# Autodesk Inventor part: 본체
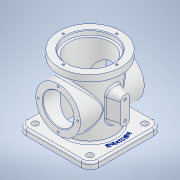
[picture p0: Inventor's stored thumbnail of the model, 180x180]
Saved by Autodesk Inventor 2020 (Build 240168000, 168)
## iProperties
Created: 2021-03
Part Number: 본체
Material: 알루미늄 6061
Document SubType Name: Modeling
Designer: USER
Density: 2.7 g/cm^3
Appearance: 알루미늄 - 평지
Mass: 830.909 g
Surface Area: 863.889 cm^2
Volume: 307.744 cm^3
Author: USER
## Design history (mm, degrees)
sketch "스케치1"
  geometry: L1 (57, -57)-(-57, -57); L2 (-57, -57)-(-57, 57); L3 (-57, 57)-(57, 57); L4 (57, 57)-(57, -57); L5 (57, -57)-(-57, 57); L6 (-57, -57)-(57, 57); 1 further point
  constraints: 12 end point, 2 midpoint, 2 parallel, 1 horizontal, 1 perpendicular
  dimensions: "d0" = 114 distance of L1.start L1.end; "d1" = 114 distance of L1.end L2.end
extrude "돌출1" new body sketch "스케치1" distance "d2" = 10; taper "d3" = 0 deg
sketch "스케치2"
  geometry: C1 r 38 at (0, 0); 1 further point
  constraints: 1 centre point, 1 coincident
  dimensions: "d4" = 76 diameter of C1
extrude "돌출2" join sketch "스케치2" distance "d5" = 101; taper "d6" = 0 deg
sketch "스케치3"
  geometry: C1 r 49 at (0, 0); 1 further point
  constraints: 1 centre point, 1 coincident
  dimensions: "d7" = 98 diameter of C1
extrude "돌출3" join sketch "스케치3" distance "d8" = 13; taper "d9" = 0 deg
sketch "스케치4"
  geometry: L1 (57, 0)-(-57, 0) reference; C1 r 35 at (0, 54); 2 further points
  constraints: 1 centre point, 1 midpoint, 1 vertical alignment
  dimensions: "d10" = 54 distance from line of C1.centre L1; "d11" = 70 diameter of C1
extrude "돌출4" join sketch "스케치4" stored distance "d12" = 100; taper "d13" = 0 deg
sketch "스케치5"
  geometry: C1 r 38 at (0, 0) reference; 2 further points
  constraints: 1 coincident
hole "구멍1" sketch "스케치5" at (0, 0) diameter "d14" = 66; stored, may be unused: countersink angle "d18" = 90 deg, drill point angle "d20" = 118 deg; dims "d15" = 6, "d16" = 74, "d17" = 7, "d19" = 8
sketch "스케치6"
  geometry: C1 r 35 at (0, 0) reference; 2 further points
  constraints: 1 coincident
hole "구멍2" sketch "스케치6" at (0, 0) diameter "d21" = 48; stored, may be unused: countersink angle "d25" = 90 deg, drill point angle "d27" = 118 deg; dims "d22" = 6, "d23" = 74, "d24" = 7, "d26" = 8
sketch "스케치7" dims "d28" = 62
  geometry: C1 r 35 at (0, 0) reference; 3 further points
  constraints: 2 vertical alignment, 1 coincident, 2 other
hole "구멍3" sketch "스케치7" at (0, 31) diameter "d29" = 3.242; stored, may be unused: countersink angle "d33" = 90 deg, drill point angle "d35" = 118 deg; dims "d30" = 6, "d31" = 74, "d32" = 7, "d34" = 8
sketch "스케치8" dims "d39" = 84
  geometry: C1 r 49 at (0, 0) reference; 3 further points
  constraints: 2 horizontal alignment, 1 coincident, 2 other
hole "구멍4" sketch "스케치8" at (-42, 0) diameter "d40" = 3.242; stored, may be unused: countersink angle "d44" = 90 deg, drill point angle "d46" = 118 deg; dims "d41" = 6, "d42" = 74, "d43" = 7, "d45" = 8
fillet "모깎기1" dims "d50" = 14
sketch "스케치9"
  geometry: A1 r 14 centre (-43, -43) between (-57, -43) and (-43, -57) reference; A2 r 14 centre (-43, 43) between (-43, 57) and (-57, 43) reference; A3 r 14 centre (43, 43) between (57, 43) and (43, 57) reference; A4 r 14 centre (43, -43) between (43, -57) and (57, -43) reference; 5 further points
  constraints: 4 coincident
hole "구멍5" sketch "스케치9" at (-43, -43), (-43, 43), (43, 43), (43, -43) diameter "d51" = 10; stored, may be unused: countersink angle "d55" = 90 deg, drill point angle "d57" = 118 deg; dims "d52" = 6, "d53" = 74, "d54" = 7, "d56" = 8
node "작업 평면1"
sketch "스케치10"
  geometry: L1 (70, 0)-(41, 0); L2 (70, 7)-(41, 7); L3 (41, -7)-(70, -7); L4 (0, 43)-(0, -43) reference; L5 (0, 43)-(0, 57) reference; A1 r 7 centre (70, 0) between (70, -7) and (70, 7); A2 r 7 centre (41, 0) between (41, 7) and (41, -7); 3 further points
  constraints: 8 end point, 4 point on circle, 4 tangent, 2 centre point, 2 midpoint, 1 horizontal, 1 horizontal alignment, 1 parallel
  dimensions: "d60" = 14 distance between parallel lines of L3 L2; "d63" = 55.5 distance from line of L5 point (55.5, 0); "d64" = 43 dimension on A2 A1
extrude "돌출5" join sketch "스케치10" stored distance "d65" = 100; taper "d66" = 15 deg
sketch "스케치11"
  geometry: A1 r 7 centre (0, 70) between (7, 70) and (-7, 70) reference; A2 r 7 centre (0, 41) between (-7, 41) and (7, 41) reference; 3 further points
  constraints: 2 coincident
hole "구멍6" sketch "스케치11" at (0, 70), (0, 41) diameter "d67" = 4.134; stored, may be unused: countersink angle "d71" = 90 deg, drill point angle "d73" = 118 deg; dims "d68" = 8, "d69" = 74, "d70" = 7, "d72" = 10
chamfer "모따기1" distance "d74" = 1; stored, may be unused: second distance "d75" = 2, angle "d76" = 45 deg
chamfer "모따기2" distance "d77" = 1; stored, may be unused: second distance "d78" = 2, angle "d79" = 45 deg
fillet "모깎기2" dims "d80" = 3
sketch "스케치12"
  geometry: C1 r 33 at (0, 0) reference; C2 r 50 at (0, 0); 1 further point
  constraints: 1 centre point, 1 coincident, 1 other
  dimensions: "d81" = 100 diameter of C2
feature "엠보싱1" sketch "스케치12" dims "d0" = 114, "d1" = 114, "d10" = 54, "d11" = 70, "d82" = 0.5, "d83" = 0
node "솔리드1"
pattern_circular "원형 패턴1" dims angle "d37" = 360 deg
mirror "미러1"
pattern_circular "원형 패턴2" dims angle "d48" = 360 deg
feature "A9D066F2-1C7D-4E18-AEED-F7BC21143FA4" dims "d21" = 48, "d22" = 6, "d23" = 74, "d24" = 7, "d25" = 90 deg, "d26" = 8, "d27" = 118 deg
other parameters: "d58" = 55
